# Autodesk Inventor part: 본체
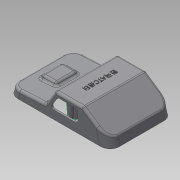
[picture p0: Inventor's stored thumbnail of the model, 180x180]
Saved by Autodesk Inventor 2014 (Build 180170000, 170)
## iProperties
Created: 2015-05
Part Number: 본체
Material: Generic
Document SubType Name: Modeling
Designer: Administrator
Density: 1 g/cm^3
Appearance: Default
Author: Administrator
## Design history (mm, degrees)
sketch "스케치1"
  geometry: L1 (61, 0)-(-61, 0); L2 (-61, 0)-(-58.321, 10); L3 (-58.321, 10)-(-28.321, 30); L4 (-28.321, 30)-(4.842, 30); L5 (61, 0)-(58.588, 9); L6 (58.588, 9)-(16.588, 11.201); L7 (4.842, 30)-(16.588, 11.201); 2 further points
  constraints: 14 end point, 1 coincident, 1 horizontal, 1 midpoint, 1 parallel
  dimensions: "d0" = 122 distance of L1.start L1.end; "d1" = 105 deg angle of L1 L2; "d2" = 20 vertical distance of L2.end L3.end; "d3" = 30 vertical distance of L1.end L3.end; "d4" = 30 horizontal distance of L2.end L3.end; "d5" = 9 vertical distance of L1.start L5.end; "d6" = 105 deg angle of L1 L5; "d7" = 3 deg angle of L1 L6; "d8" = 42 horizontal distance of L5.end L6.end; "d9" = 125 deg angle of L6 L7
extrude "돌출1" new body sketch "스케치1" stored distance "d10" = 76; taper "d11" = 0 deg
sketch "스케치2"
  geometry: L1 (58.588, 9)-(16.588, 11.201) reference; L2 (47.588, 9.576)-(46.236, 14); L3 (27.588, 10.625)-(29.021, 14); L4 (46.236, 14)-(29.021, 14); 1 further point
  constraints: 6 end point, 2 point on line
  dimensions: "d12" = 5 vertical distance of L2.end L1.start; "d13" = 11 horizontal distance of L2.start L1.start; "d14" = 20 horizontal distance of L3.start L2.start; "d15" = 70 deg angle of L1 L3; "d16" = 70 deg angle of L1 L2; "d17" = 5 vertical distance of L1.start L3.end
extrude "돌출2" join sketch "스케치2" stored distance "d18" = 26; taper "d19" = 0 deg
fillet "모깎기1" dims "d20" = 12
fillet "모깎기2" dims "d21" = 3
fillet "모깎기3" dims "d22" = 3
fillet "모깎기4" dims "d23" = 3
sketch "스케치3" dims "d29" = 4
  geometry: L1 (64.179, 61)-(64.179, 9) reference; L2 (30.591, 73)-(0, 73) reference; 2 further points
  constraints: 1 other
  dimensions: "d24" = 50 distance from line of point (14.179, 35) L1; "d25" = 38 distance from line of point (14.179, 35) L2
feature "엠보싱1" sketch "스케치3" dims "d0" = 122, "d1" = 105 deg, "d2" = 20, "d3" = 30, "d4" = 30, "d5" = 9, "d6" = 105 deg, "d7" = 3 deg, "d8" = 42, "d9" = 125 deg, "d26" = 0.5, "d27" = 0
feature "쉘1" dims "d28" = 2
sketch "스케치4"
  geometry: A1 r 2 centre (0, 47) between (0, 45) and (0, 49); A2 r 2 centre (0, 36) between (0, 34) and (0, 38); A3 r 2 centre (0, 16) between (0, 14) and (0, 18); A4 r 2 centre (0, 5) between (0, 3) and (0, 7); 3 further points
  constraints: 8 point on circle, 4 centre point, 13 other
  dimensions: "d29" = 4 diameter of A1; "d30" = 4 diameter of A2; "d31" = 4 diameter of A3; "d32" = 4 diameter of A4; "d33" = 10 vertical distance of A2.centre point (15.788, 26); "d34" = 20 distance of A2.centre A3.centre; "d35" = 11 distance of A3.centre A4.centre; "d36" = 11 distance of A1.centre A2.centre
extrude "돌출3" join sketch "스케치4" distance "d37" = 2; taper "d38" = 0 deg
chamfer "모따기1" distance "d39" = 1; stored, may be unused: second distance "d40" = 2, angle "d41" = 45 deg
node "작업 평면1"
sketch "스케치6"
  geometry: L1 (5.723, 28.59)-(15.761, 12.526) reference; L2 (-27.412, 30)-(3.179, 30) reference; L3 (-46.036, 18.19)-(-29.076, 29.496) reference; L4 (2.951, 23.59)-(8.575, 14.59); L5 (-19.557, 25)-(0.407, 25); L6 (-22.557, 22)-(-22.557, 13); L7 (-19.557, 10)-(6.031, 10); A1 r 3 centre (0.407, 22) between (2.951, 23.59) and (0.407, 25); A2 r 3 centre (0.407, 22) between (2.951, 23.59) and (0.407, 25); A3 r 3 centre (-19.557, 22) between (-19.557, 25) and (-22.557, 22); A4 r 3 centre (-19.557, 13) between (-22.557, 13) and (-19.557, 10); A5 r 3 centre (6.031, 13) between (6.031, 10) and (8.575, 14.59); 4 further points
  constraints: 10 point on circle, 10 tangent, 8 end point, 8 point on line, 5 centre point, 3 equal radius, 2 parallel, 2 perpendicular
  dimensions: "d80" = 5 distance between parallel lines of L5 L2; "d81" = 5 distance between parallel lines of L1 L4; "d82" = 3 radius of A1; "d83" = 34 distance of point (-22.557, 10) point (11.443, 10); "d84" = 15 distance of point (-22.557, 10) point (-22.557, 25); "d85" = 3 radius of A3
sketch "스케치7"
  geometry: L1 (27.412, 27)-(44.372, 15.694) reference; L2 (-3.179, 27)-(27.412, 27) reference; L3 (-13.217, 10.936)-(-3.179, 27) reference; L4 (-46.805, 6.613)-(-17.991, 8.124) reference; L5 (-48.577, 0)-(-46.805, 6.613) reference; L6 (-48.577, 0)-(48.577, 0) reference; L7 (44.372, 15.694)-(48.577, 0) reference; A1 r 6 centre (-18.305, 14.115) between (-17.991, 8.124) and (-13.217, 10.936) reference; 3 further points
  dimensions: "d79" = 122 distance of point (-60.934, 0) point (61.066, 0)
extrude "돌출5" cut sketch "스케치6" distance "d86" = 2; taper "d87" = 0 deg
sketch "스케치9"
  geometry: L1 (107.506, 64)-(107.506, 12) reference; L2 (97.153, 2)-(0, 2) reference; L3 (-10.353, 12)-(-10.353, 64) reference; L4 (0, 74)-(97.153, 74) reference; L5 (-12.423, 64)-(-12.423, 12) reference; L6 (97.153, 0)-(0, 0) reference; L7 (109.577, 12)-(109.577, 15) reference; L8 (109.577, 15)-(109.577, 19) reference; L9 (109.577, 19)-(109.577, 26) reference; L10 (109.577, 26)-(109.577, 30) reference; L11 (109.577, 30)-(109.577, 46) reference; L12 (109.577, 46)-(109.577, 50) reference; L13 (109.577, 50)-(109.577, 57) reference; L14 (109.577, 57)-(109.577, 61) reference; L15 (109.577, 61)-(109.577, 64) reference; L16 (0, 76)-(97.153, 76) reference; L17 (-11.423, 12)-(-11.423, 64); L18 (0, 75)-(97.153, 75); L19 (108.577, 64)-(108.577, 61); L20 (108.577, 61)-(108.577, 57); L21 (108.577, 57)-(108.577, 50); L22 (108.577, 50)-(108.577, 46); L23 (108.577, 46)-(108.577, 30); L24 (108.577, 30)-(108.577, 26); L25 (108.577, 26)-(108.577, 19); L26 (108.577, 19)-(108.577, 15); L27 (108.577, 15)-(108.577, 12); L28 (97.153, 1)-(0, 1); 9 further points; 8 other entities
  constraints: 24 end point, 7 parallel, 28 other
  dimensions: "d88" = 1 distance between parallel lines of L6 L28
extrude "돌출6" join sketch "스케치9" distance "d89" = 1; taper "d90" = 0 deg
node "작업 평면2"
sketch "스케치10"
  geometry: C1 r 3 at (-40, 0); C2 r 3 at (0, -22); C3 r 3 at (0, 22); C4 r 3 at (40, 0); 1 further point
  constraints: 4 centre point, 2 horizontal alignment, 2 vertical alignment
  dimensions: "d92" = 6 diameter of C1; "d93" = 6 diameter of C2; "d94" = 6 diameter of C3; "d95" = 6 diameter of C4; "d96" = 22 vertical distance of C3.centre C1.centre; "d97" = 22 vertical distance of C2.centre C1.centre; "d98" = 40 distance of point (0, 0) C4.centre; "d99" = 40 distance of point (0, 0) C1.centre
extrude "돌출7" join sketch "스케치10" stored distance "d100" = 1; taper "d101" = 0 deg
sketch "스케치11"
  geometry: L1 (-45, 21)-(-35, 21); L2 (-35, 21)-(-35, 23); L3 (-35, 23)-(-45, 23); L4 (-45, 23)-(-45, 21); L5 (-45, 21)-(-35, 23); L6 (-35, 21)-(-45, 23); L7 (-5, 45)-(5, 45); L8 (5, 45)-(5, 43); L9 (5, 43)-(-5, 43); L10 (-5, 43)-(-5, 45); L11 (-5, 45)-(5, 43); L12 (5, 45)-(-5, 43); L13 (45, 21)-(35, 21); L14 (35, 21)-(35, 23); L15 (35, 23)-(45, 23); L16 (45, 23)-(45, 21); L17 (45, 21)-(35, 23); L18 (35, 21)-(45, 23); L19 (5, -1)-(-5, -1); L20 (-5, -1)-(-5, 1); L21 (-5, 1)-(5, 1); L22 (5, 1)-(5, -1); L23 (5, -1)-(-5, 1); L24 (-5, -1)-(5, 1); C1 r 3 at (0, 0) reference; C2 r 3 at (0, 44) reference; C3 r 3 at (40, 22) reference; C4 r 3 at (-40, 22) reference; 1 further point
  constraints: 48 end point, 8 midpoint, 8 parallel, 4 horizontal, 4 perpendicular
  dimensions: "d102" = 10 distance of L3.end L2.end; "d103" = 2 distance of L2.end L1.end; "d104" = 10 distance of L8.end L9.end; "d105" = 2 distance of L7.end L8.end; "d106" = 10 distance of L14.end L15.end; "d107" = 2 distance of L13.end L14.end; "d108" = 10 distance of L20.end L21.end; "d109" = 2 distance of L19.end L20.end
extrude "돌출8" join sketch "스케치11" stored distance "d110" = 1; taper "d111" = 2.5 deg
sketch "스케치13"
  geometry: L1 (-5, -21)-(-2.828, -21) reference; L2 (-5, -23)-(-5, -21) reference; L3 (-2.828, -23)-(-5, -23) reference; L4 (5, -23)-(2.828, -23) reference; L5 (5, -21)-(5, -23) reference; L6 (2.828, -21)-(5, -21) reference; A1 r 3 centre (0, -22) between (-2.828, -23) and (2.828, -23) reference; A2 r 3 centre (0, -22) between (2.828, -21) and (-2.828, -21) reference; 1 further point
sketch "스케치14"
  geometry: L1 (-1.142, 26.17)-(0.973, 29.558) reference; L2 (0, 0)-(-1.142, 26.17) reference; L3 (0, 0)-(2.172, 0) reference; 3 further points; 1 other entity
  constraints: 2 other
node "솔리드1"
mirror "대칭1"
node "투영된 루프1"
node "투영된 루프2"
other parameters: "d61" = -38, "d91" = -2
